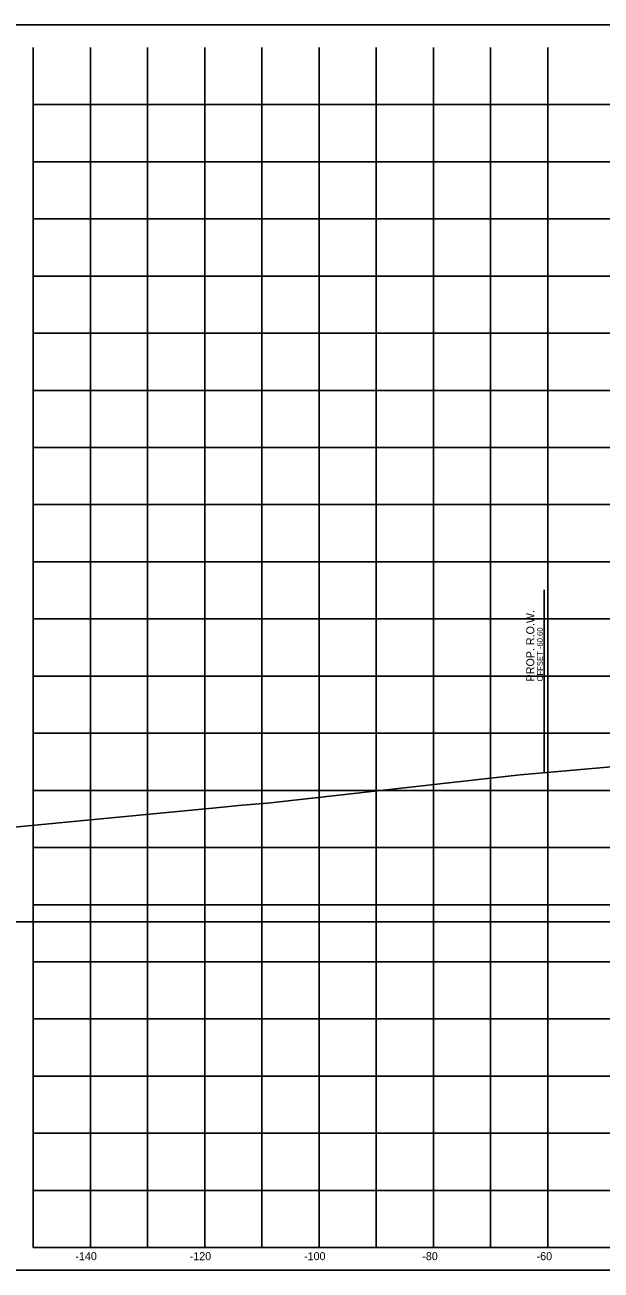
# Model space of a CAD drawing. Extents: x 5868 to 6683, y 2883 to 19120.
# Drawn here: x 6042.3 to 6143.1, y 7884.1 to 8102 of the extents above; entities that cross this region are included whole.
import ezdxf

# ---------------------------------------------------------------- set-up
doc = ezdxf.new("R2010")
doc.units = 0
for name, color, linetype in [('DESIGN - ROW - Right-of-Way and Easement Labels', 7, 'Continuous'), ('DESIGN - ROW - Right-of-Way Linework', 7, 'Continuous'), ('DESIGN - SHEET - Corner Text', 7, 'Continuous'), ('DESIGN - SHEET - Light Grid', 7, 'Continuous'), ('DESIGN - SHEET - Linework', 7, 'Continuous'), ('DESIGN - SHEET - Plot Shape', 7, 'Continuous'), ('SURVEY - GROUND - Top of Ground', 7, 'Continuous')]:
    doc.layers.add(name, color=color, linetype=linetype)

msp = doc.modelspace()

# ---------------------------------------------------------------- linework, layer by layer
at = {"layer": 'DESIGN - ROW - Right-of-Way Linework'}
msp.add_line((6133.18, 7971.14), (6133.18, 8003.14), dxfattribs=at)
at = {"layer": 'DESIGN - SHEET - Light Grid'}
msp.add_line((5893.78, 7945.07), (6193.78, 7945.07), dxfattribs=at)
at = {"layer": 'DESIGN - SHEET - Linework'}
for p, q in [((6053.78, 7888.07), (6053.78, 8098.07)), ((6063.78, 7888.07), (6063.78, 8098.07)), ((6073.78, 7888.07), (6073.78, 8098.07)), ((6083.78, 7888.07), (6083.78, 8098.07)), ((6093.78, 7888.07), (6093.78, 8098.07)), ((6103.78, 7888.07), (6103.78, 8098.07)), ((6113.78, 7888.07), (6113.78, 8098.07)), ((6123.78, 7888.07), (6123.78, 8098.07)), ((6133.78, 7888.07), (6133.78, 8098.07)), ((6043.78, 8088.07), (6343.78, 8088.07)), ((6043.78, 8078.07), (6343.78, 8078.07)), ((6043.78, 8068.07), (6343.78, 8068.07)), ((6043.78, 8058.07), (6343.78, 8058.07)), ((6043.78, 8048.07), (6343.78, 8048.07)), ((6043.78, 8038.07), (6343.78, 8038.07)), ((6043.78, 8028.07), (6343.78, 8028.07)), ((6043.78, 8018.07), (6343.78, 8018.07)), ((6043.78, 8008.07), (6343.78, 8008.07)), ((6043.78, 7998.07), (6343.78, 7998.07)), ((6043.78, 7988.07), (6343.78, 7988.07)), ((6043.78, 7978.07), (6343.78, 7978.07)), ((6043.78, 7968.07), (6343.78, 7968.07)), ((6043.78, 7958.07), (6343.78, 7958.07)), ((6043.78, 7948.07), (6343.78, 7948.07)), ((6043.78, 7938.07), (6343.78, 7938.07)), ((6043.78, 7928.07), (6343.78, 7928.07)), ((6043.78, 7918.07), (6343.78, 7918.07)), ((6043.78, 7908.07), (6343.78, 7908.07)), ((6043.78, 7898.07), (6343.78, 7898.07))]:
    msp.add_line(p, q, dxfattribs=at)
msp.add_lwpolyline([(6043.78, 8098.07), (6043.78, 7888.07), (6343.78, 7888.07), (6343.78, 8098.07)], dxfattribs=at)
at = {"layer": 'DESIGN - SHEET - Plot Shape'}
msp.add_lwpolyline([(6023.78, 8102.01), (6363.78, 8102.01), (6363.78, 7884.13), (6023.78, 7884.13)], close=True, dxfattribs=at)
at = {"layer": 'SURVEY - GROUND - Top of Ground'}
msp.add_lwpolyline([(6008.71, 7958.61), (6061.75, 7963.7), (6075.75, 7965.01), (6080.33, 7965.46), (6084.78, 7965.84), (6118.08, 7969.58), (6128.97, 7970.78), (6158.19, 7973.33)], dxfattribs=at)

# ---------------------------------------------------------------- texts
at = {"layer": 'DESIGN - ROW - Right-of-Way and Easement Labels'}
for s, height, p in [('PROP. R.O.W.', 1.4, (6131.43, 7987.14)), ('OFFSET -60.60', 1, (6132.93, 7987.14))]:
    msp.add_text(s, height=height, rotation=90, dxfattribs=at).set_placement(p)
at = {"layer": 'DESIGN - SHEET - Corner Text'}
for s, p in [('-140', (6051.16, 7885.87)), ('-120', (6071.16, 7885.87)), ('-100', (6091.16, 7885.87)), ('-80', (6111.84, 7885.87)), ('-60', (6131.84, 7885.87))]:
    msp.add_text(s, height=1.4, dxfattribs=at).set_placement(p)

doc.saveas('drawing.dxf')
